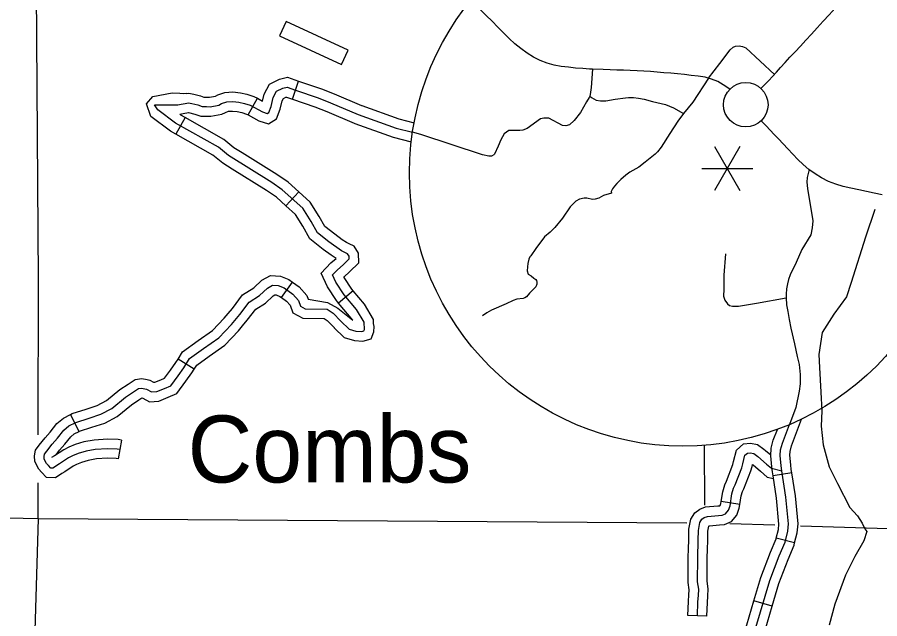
# Model space of a CAD drawing. Extents: x 0 to 3171, y 0 to 2059.
# Drawn here: x 1093.1 to 1206.3, y 496.2 to 575.3 of the extents above; entities that cross this region are included whole.
import ezdxf

# ---------------------------------------------------------------- set-up
doc = ezdxf.new("R2010")
doc.units = 0
for name, color, linetype in [('Level 10', 7, 'Continuous'), ('Level 24', 7, 'Continuous'), ('Level 32', 7, 'Continuous'), ('Level 35', 7, 'Continuous'), ('Level 45', 7, 'Continuous'), ('Level 48', 7, 'Continuous'), ('Level 5', 7, 'Continuous'), ('Level 57', 7, 'Continuous'), ('Level 63', 7, 'Continuous')]:
    doc.layers.add(name, color=color, linetype=linetype)

msp = doc.modelspace()

# ---------------------------------------------------------------- linework, layer by layer
at = {"layer": 'Level 10'}
for points in [[(1190.74, 565.9), (1191.3, 566.48), (1191.76, 566.96), (1192.25, 567.48), (1192.78, 568.04), (1193.33, 568.65), (1193.93, 569.3), (1194.55, 570), (1195.22, 570.72), (1195.92, 571.48), (1196.64, 572.26), (1197.38, 573.06), (1198.13, 573.89), (1198.9, 574.73), (1199.69, 575.58), (1200.48, 576.44), (1201.28, 577.31), (1202.08, 578.18), (1204.91, 581.19)], [(1170.04, 568.39), (1168.63, 568.45), (1168.24, 568.46), (1167.33, 568.51), (1166.4, 568.59), (1165.46, 568.69), (1164.52, 568.81), (1163.58, 568.97), (1162.65, 569.23), (1161.74, 569.58), (1160.86, 570.03), (1160.02, 570.55), (1159.22, 571.14), (1158.44, 571.79), (1157.68, 572.48), (1156.93, 573.22), (1156.18, 573.97), (1155.43, 574.73), (1154.67, 575.48), (1153.91, 576.23), (1153.15, 576.98), (1152.63, 577.5)], [(1183.68, 567.31), (1183.4, 567.39), (1182.51, 567.53), (1181.6, 567.63), (1180.69, 567.73), (1179.79, 567.82), (1178.89, 567.9), (1178.01, 567.98), (1177.12, 568.06), (1176.23, 568.14), (1175.34, 568.2), (1174.47, 568.22), (1173.56, 568.28), (1172.69, 568.31), (1171.81, 568.33), (1170.93, 568.35), (1170.04, 568.39)], [(1186.66, 565.8), (1185.8, 566.4), (1185.06, 566.82), (1184.26, 567.15), (1183.68, 567.31)], [(1206.66, 551.93), (1205.63, 552.15), (1204.61, 552.37), (1203.58, 552.58), (1202.56, 552.79), (1201.55, 553.02), (1200.56, 553.32), (1199.62, 553.7), (1198.71, 554.16), (1197.85, 554.68), (1197.04, 555.27), (1196.29, 555.91), (1195.6, 556.59), (1194.93, 557.28), (1194.29, 557.97), (1193.67, 558.63), (1193.07, 559.27), (1192.5, 559.87), (1191.95, 560.45), (1191.44, 560.99), (1190.78, 561.67)]]:
    msp.add_lwpolyline(points, dxfattribs=at)
at = {"layer": 'Level 24'}
msp.add_circle((1188.75, 563.77), 2.92, dxfattribs=at)
at = {"layer": 'Level 32'}
for p, q in [((1194.8, 515.4), (1192.33, 515.01)), ((1195.17, 506.19), (1192.75, 506.81)), ((1192.21, 497.87), (1189.81, 498.57))]:
    msp.add_line(p, q, dxfattribs=at)
for points in [[(1183.86, 567.26), (1185.36, 569.17), (1186.71, 570.99), (1187.11, 571.34), (1187.42, 571.47), (1187.87, 571.5), (1188.32, 571.44), (1188.77, 571.23), (1192.51, 567.76)], [(1183.86, 567.26), (1181.81, 564.1), (1180.57, 562.64), (1179.83, 561.61), (1178.77, 560.01), (1177.64, 558.18), (1177.17, 557.57), (1176.87, 557.28), (1175.54, 556.22), (1174.7, 555.57), (1173.52, 554.89), (1172.99, 554.5), (1172.32, 553.93), (1171.81, 553.43), (1171.5, 553.08), (1171.24, 552.72), (1171.09, 552.35), (1171.11, 552.17)], [(1197.07, 555.25), (1196.82, 554.19), (1196.79, 553.61), (1196.85, 552.76), (1197.57, 548.53), (1197.46, 547.58), (1197.29, 546.69), (1196.12, 544.73), (1195.37, 543.04), (1195.14, 542.55), (1194.84, 541.99), (1194.59, 541.44), (1194.37, 540.79), (1194.22, 540.24), (1194.1, 539.6), (1194.04, 538.86), (1194.05, 538.42), (1194.1, 537.49), (1194.26, 536.61), (1194.46, 535.57), (1194.68, 534.42), (1195.16, 532.37), (1195.52, 530.69), (1195.76, 529.65), (1195.89, 528.33), (1195.88, 527.1), (1195.76, 526.12), (1195.34, 524.01), (1194.48, 521.74)], [(1194.8, 515.4), (1194.73, 515.86), (1194.66, 516.47), (1194.53, 517.71), (1194.57, 518.23), (1194.75, 518.94), (1196.09, 522.47)], [(1190.08, 495.07), (1191.9, 501.24), (1193.14, 504.51), (1193.91, 506.31), (1194.29, 507.75), (1194.36, 508.69), (1194.03, 512.22), (1193.49, 515.69), (1193.42, 516.34), (1193.28, 517.68), (1193.33, 518.43), (1193.56, 519.32), (1194.48, 521.74)], [(1192.33, 515.01), (1192.25, 515.53), (1192.18, 516.21), (1192.03, 517.66), (1192.09, 518.63), (1192.37, 519.71), (1192.9, 521.12)], [(1192.75, 506.81), (1193.05, 507.95), (1193.1, 508.67), (1192.79, 512.07), (1192.33, 515.01)], [(1195.17, 506.19), (1195.52, 507.54), (1195.61, 508.7), (1195.27, 512.37), (1194.8, 515.4)], [(1189.81, 498.57), (1190.71, 501.64), (1191.98, 504.98), (1192.73, 506.72), (1192.75, 506.81)], [(1192.21, 497.87), (1193.08, 500.85), (1194.3, 504.04), (1195.1, 505.9), (1195.17, 506.19)], [(1187.32, 490.12), (1187.71, 491.5), (1188.88, 495.43), (1189.81, 498.57)], [(1189.73, 489.44), (1190.11, 490.81), (1191.28, 494.72), (1192.21, 497.87)]]:
    msp.add_lwpolyline(points, dxfattribs=at)
at = {"layer": 'Level 35'}
msp.add_lwpolyline([(1205.7, 550), (1204.46, 546.35), (1202.61, 540.42), (1201.96, 538.54), (1200.32, 536.25), (1198.78, 533.83), (1198.36, 530.97), (1198.43, 529.24), (1198.61, 526), (1198.75, 523.56), (1198.65, 521.54), (1198.92, 519.09), (1199.71, 516.21), (1200.81, 513.99), (1202.41, 510.86), (1203.43, 509.77), (1204.04, 508.79), (1204.38, 508.05), (1204.64, 507.69), (1204.26, 506.47), (1203.09, 504.41), (1201.83, 501.98), (1200.46, 498.14), (1199.72, 495.39)], dxfattribs=at)
at = {"layer": 'Level 45'}
for p, q in [((1129.2, 564.52), (1130.02, 566.88)), ((1123.4, 562.43), (1124.6, 564.62)), ((1115.11, 562.09), (1113.88, 559.91)), ((1130.04, 552.34), (1128.36, 550.49)), ((1127.77, 538.43), (1129.23, 540.46)), ((1137.19, 539.32), (1135.28, 537.71)), ((1116.3, 529.03), (1114.18, 530.35)), ((1101.19, 520.84), (1100.07, 523.08)), ((1106.77, 519.69), (1106.33, 517.23)), ((1187.98, 511.23), (1185.51, 511.63)), ((1183.65, 496.59), (1181.16, 496.68))]:
    msp.add_line(p, q, dxfattribs=at)
for points in [[(1168.63, 568.45), (1168.46, 566.02), (1168.33, 565.13), (1168.28, 564.9), (1168.18, 564.74), (1167.84, 564.17), (1167.04, 562.77), (1166.21, 561.7), (1165.61, 561.14), (1165.11, 560.99), (1164.7, 561.03), (1162.9, 562), (1162.24, 562.01), (1161.77, 561.94), (1160.04, 560.63), (1159.45, 560.43), (1159.06, 560.39), (1157.65, 560.39), (1157.02, 559.96), (1156.59, 559.18), (1156.25, 558.31), (1155.75, 557.26), (1155.65, 557.18), (1155.37, 557.03), (1155.02, 557.02), (1154.17, 557.17), (1146.09, 559.86), (1144.97, 560.15)], [(1124.6, 564.62), (1125.28, 564.25), (1125.51, 565.18), (1126.2, 566.48), (1127.5, 567.13), (1128.57, 567.39), (1130.02, 566.88)], [(1130.02, 566.88), (1133.01, 565.84), (1134.68, 565.19), (1138.29, 563.66)], [(1113.88, 559.91), (1113.18, 560.31), (1110.62, 562.24), (1110.06, 563.87), (1110.87, 564.87), (1113.39, 565.34), (1114.44, 565.3), (1114.9, 565.23), (1115.31, 565.3)], [(1111.11, 563.74), (1113.95, 563.74), (1114.15, 563.74), (1114.61, 563.84), (1115.1, 563.94), (1115.57, 564.02), (1115.98, 563.94), (1116.77, 563.74), (1117.37, 563.53), (1117.93, 563.53), (1118.4, 563.51), (1119.53, 563.71), (1119.91, 563.92), (1120.57, 564.14), (1121.36, 564.19), (1122.17, 564.12), (1122.9, 563.94), (1123.66, 563.71), (1125.29, 562.82), (1125.9, 562.62), (1126.1, 562.75), (1126.4, 563.56), (1126.68, 564.73), (1127.11, 565.54), (1127.93, 565.94), (1128.51, 566.08), (1129.61, 565.7)], [(1115.29, 565.24), (1115.59, 565.29), (1116.25, 565.16), (1117.12, 564.94), (1117.58, 564.78), (1117.97, 564.78), (1118.32, 564.77), (1119.12, 564.91), (1119.41, 565.06), (1120.32, 565.38), (1121.37, 565.45), (1122.37, 565.35), (1123.23, 565.15), (1124.15, 564.87), (1124.6, 564.62)], [(1129.61, 565.7), (1132.58, 564.67), (1134.21, 564.03), (1137.86, 562.49), (1142.82, 560.71), (1144.97, 560.15)], [(1123.4, 562.43), (1124.79, 561.67), (1126.06, 561.25), (1127.13, 561.92), (1127.59, 563.2), (1127.86, 564.28), (1128.03, 564.6), (1128.36, 564.76), (1128.45, 564.78), (1129.2, 564.52)], [(1129.2, 564.52), (1132.14, 563.5), (1133.74, 562.87), (1137.32, 561.36)], [(1168.28, 564.9), (1168.48, 564.7), (1169.12, 564.36), (1169.69, 564.28), (1170.39, 564.29), (1171.6, 564.51), (1172.96, 564.68), (1173.36, 564.7), (1174.01, 564.7), (1174.65, 564.63), (1175.39, 564.49), (1176.51, 564.19), (1178.2, 563.78), (1179.26, 563.37), (1180.57, 562.64)], [(1125.92, 539.69), (1126.59, 540.06), (1127.35, 540.01), (1128.14, 539.7), (1129.27, 538.89), (1130.02, 538.07), (1130.28, 537.31), (1130.9, 536.96), (1133.78, 536.91), (1134.55, 536.37), (1135.58, 535.35), (1136.65, 534.3), (1137.55, 534.04), (1138.32, 533.98), (1138.6, 534.06), (1138.66, 534.23), (1138.69, 534.55), (1138.61, 534.89), (1138.61, 535.21), (1137.64, 536.85), (1136, 538.8), (1134.91, 540.47), (1134.48, 541.4), (1135.12, 542.09), (1135.88, 542.73), (1136.66, 543.51), (1136.64, 543.89), (1136.45, 544.19), (1136.1, 544.36), (1135.64, 544.59), (1134.01, 545.75), (1132.48, 546.96), (1131.66, 548.44), (1130.58, 550.16), (1127.87, 552.61), (1126.5, 553.56), (1120.79, 557.1), (1119.48, 558.19), (1113.86, 561.36), (1111.54, 563.12), (1111.11, 563.74)], [(1138.29, 563.66), (1138.32, 563.65), (1143.19, 561.9), (1145.18, 561.39)], [(1115.11, 562.09), (1114.55, 562.41), (1114.41, 562.51), (1114.87, 562.62), (1115.56, 562.76)], [(1122.62, 557.44), (1121.52, 558.12), (1120.2, 559.22), (1115.11, 562.09)], [(1115.56, 562.76), (1116.41, 562.54), (1117.17, 562.28), (1117.9, 562.28), (1118.47, 562.25), (1119.94, 562.52), (1120.41, 562.77), (1120.82, 562.91), (1121.34, 562.94), (1121.96, 562.88), (1122.58, 562.73), (1123.18, 562.55), (1123.4, 562.43)], [(1137.32, 561.36), (1137.41, 561.32), (1142.46, 559.51), (1144.81, 558.9)], [(1121.3, 555.32), (1120.06, 556.09), (1118.77, 557.16), (1113.88, 559.91)], [(1130.04, 552.34), (1128.65, 553.59), (1127.18, 554.6), (1122.62, 557.44)], [(1128.36, 550.49), (1127.1, 551.63), (1125.82, 552.51), (1121.3, 555.32)], [(1135.76, 546.04), (1134.76, 546.75), (1133.45, 547.79), (1132.74, 549.08), (1131.55, 550.97), (1130.04, 552.34)], [(1171.11, 552.17), (1170.07, 551.84), (1169.45, 551.5), (1168.97, 551.35), (1168.64, 551.34), (1167.88, 551.48), (1167.51, 551.5), (1166.92, 551.35), (1166.42, 551.11), (1166.1, 550.77), (1165.7, 550.34), (1164.66, 548.85), (1163.65, 547.63), (1163.07, 547.01), (1162.3, 546.43), (1161.19, 544.88), (1160.51, 543.9), (1160.41, 543.77), (1160.26, 543.49), (1160.12, 542.92), (1160.06, 542.49), (1160.03, 541.96), (1160.17, 541.53), (1160.56, 541.27), (1160.93, 540.98), (1161.17, 540.82), (1161.26, 540.69), (1161.32, 540.47), (1161.32, 540.19), (1161.16, 539.84), (1160.77, 539.45), (1160.33, 539.01), (1159.93, 538.55), (1159.75, 538.42), (1159.51, 538.33), (1158.66, 538.23), (1158.2, 538.06), (1157.3, 537.63), (1155.34, 536.8), (1154.74, 536.41), (1154.18, 536.04)], [(1134.31, 544), (1133.26, 544.75), (1131.5, 546.14), (1130.58, 547.81), (1129.62, 549.35), (1128.36, 550.49)], [(1137.19, 539.32), (1137, 539.55), (1136.01, 541.07), (1135.97, 541.16), (1135.99, 541.18), (1136.72, 541.81), (1137.93, 543.01), (1137.88, 544.29), (1137.3, 545.17), (1136.65, 545.48), (1136.29, 545.66), (1135.76, 546.04)], [(1135.28, 537.71), (1134.99, 538.05), (1133.81, 539.86), (1133, 541.63), (1134.26, 542.99), (1134.93, 543.56), (1134.31, 544)], [(1186.09, 544.18), (1185.85, 541.39), (1185.85, 539.55), (1185.84, 538.63), (1186.01, 538.1), (1186.33, 537.6), (1186.6, 537.4), (1187, 537.29), (1187.81, 537.31), (1190.14, 537.71), (1194.05, 538.42)], [(1120.76, 536.33), (1121.33, 537.01), (1122.66, 538.79), (1124.12, 539.71), (1125.17, 540.7), (1126.31, 541.33), (1127.63, 541.24), (1128.75, 540.8), (1129.23, 540.46)], [(1129.23, 540.46), (1130.11, 539.83), (1131.12, 538.72), (1131.29, 538.21), (1133.81, 537.8), (1135.17, 537.05), (1137.16, 535.48)], [(1106.55, 518.46), (1106.19, 518.53), (1104.92, 518.58), (1103.3, 518.48), (1102.1, 518.25), (1101.07, 517.93), (1100.34, 517.63), (1099.8, 517.36), (1098.63, 516.6), (1097.74, 516.03), (1097.46, 516.04), (1097.15, 516.37), (1096.91, 516.62), (1096.6, 517.21), (1096.59, 517.55), (1096.65, 517.87), (1096.96, 518.27), (1097.67, 519.19), (1098.37, 519.96), (1099.19, 521.01), (1099.82, 521.56), (1100.76, 522.03), (1102.49, 522.59), (1104.06, 523.1), (1105.48, 523.86), (1107.3, 525.33), (1109.01, 526.48), (1109.37, 526.53), (1109.83, 526.43), (1110.03, 526.38), (1110.69, 526.03), (1111.4, 526.08), (1112.41, 526.48), (1113.23, 526.84), (1114.19, 528.16), (1114.95, 529.22), (1115.71, 530.44), (1117.54, 531.76), (1119.52, 533.13), (1121.19, 534.91), (1122.31, 536.23), (1123.52, 537.85), (1124.89, 538.72), (1125.92, 539.69)], [(1134.67, 534.5), (1134.7, 534.47), (1135.99, 533.18), (1137.34, 532.8), (1138.44, 532.72), (1139.54, 533.02), (1139.89, 533.95), (1139.95, 534.63), (1139.86, 535.04), (1139.85, 535.56), (1138.66, 537.58), (1137.19, 539.32)], [(1122.67, 534.72), (1123.28, 535.45), (1124.39, 536.92), (1125.66, 537.72), (1126.66, 538.67), (1126.88, 538.79), (1127.07, 538.78), (1127.54, 538.59), (1127.77, 538.43)], [(1127.77, 538.43), (1128.43, 537.95), (1128.92, 537.42), (1129.25, 536.45), (1130.57, 535.72), (1133.38, 535.67), (1133.75, 535.41), (1134.67, 534.5)], [(1137.16, 535.48), (1135.28, 537.71)], [(1114.18, 530.35), (1114.78, 531.31), (1116.82, 532.78), (1118.7, 534.09), (1120.26, 535.74), (1120.76, 536.33)], [(1116.3, 529.03), (1116.64, 529.57), (1118.26, 530.74), (1120.34, 532.18), (1122.12, 534.08), (1122.67, 534.72)], [(1107.63, 527.05), (1108.55, 527.68), (1109.42, 527.8), (1110.11, 527.65), (1110.48, 527.56), (1110.96, 527.3), (1111.12, 527.31), (1111.93, 527.64), (1112.41, 527.85), (1113.18, 528.89), (1113.91, 529.92), (1114.18, 530.35)], [(1109.02, 524.98), (1109.41, 525.24), (1109.54, 525.21), (1109.57, 525.21), (1110.42, 524.75), (1111.68, 524.84), (1112.9, 525.33), (1114.04, 525.83), (1115.2, 527.43), (1115.99, 528.53), (1116.3, 529.03)], [(1100.07, 523.08), (1100.29, 523.19), (1102.1, 523.78), (1103.57, 524.25), (1104.79, 524.9), (1106.56, 526.34), (1107.63, 527.05)], [(1101.19, 520.84), (1101.23, 520.87), (1102.87, 521.4), (1104.55, 521.94), (1106.17, 522.81), (1108.05, 524.32), (1109.02, 524.98)], [(1098.93, 515.3), (1098.08, 514.76), (1096.91, 514.81), (1096.24, 515.51), (1095.88, 515.89), (1095.36, 516.88), (1095.33, 517.65), (1095.48, 518.39), (1095.96, 519.03), (1096.72, 519.99), (1097.41, 520.76), (1098.28, 521.88), (1099.12, 522.61), (1100.07, 523.08)], [(1098.16, 517.78), (1098.63, 518.38), (1099.33, 519.16), (1100.1, 520.15), (1100.52, 520.51), (1101.19, 520.84)], [(1106.77, 519.69), (1106.32, 519.77), (1104.91, 519.83), (1103.15, 519.72), (1101.8, 519.46), (1100.65, 519.11), (1099.83, 518.76), (1099.18, 518.45), (1097.95, 517.65), (1097.57, 517.4)], [(1185.51, 511.63), (1185.72, 512.91), (1185.98, 513.83), (1186.2, 514.3), (1187.04, 516.48), (1187.16, 516.89), (1187.52, 518.39), (1188.46, 519.21), (1189.36, 519.29), (1190.3, 519.14), (1191.14, 518.52), (1191.36, 518.33)], [(1182.4, 496.63), (1182.47, 498.45), (1182.52, 499.29), (1182.57, 500.11), (1182.43, 501.09), (1182.45, 504.23), (1182.51, 506.56), (1182.52, 507.85), (1182.73, 508.86), (1182.99, 509.31), (1183.3, 509.54), (1183.71, 509.69), (1185.19, 509.81), (1185.66, 509.86), (1186.1, 510.04), (1186.47, 510.49), (1186.68, 511.07), (1186.94, 512.64), (1187.15, 513.39), (1187.35, 513.81), (1188.23, 516.08), (1188.37, 516.57), (1188.64, 517.71), (1188.98, 518), (1189.32, 518.03), (1189.8, 517.96), (1190.35, 517.55), (1191.49, 516.56), (1192.14, 516), (1193.49, 515.69)], [(1191.36, 518.33), (1192.02, 517.76)], [(1106.33, 517.23), (1106.05, 517.28), (1104.93, 517.33), (1103.46, 517.23), (1102.4, 517.03), (1101.5, 516.75), (1100.86, 516.49), (1100.42, 516.27), (1099.31, 515.55), (1098.93, 515.3)], [(1187.98, 511.23), (1188.16, 512.37), (1188.33, 512.95), (1188.5, 513.32), (1189.41, 515.68), (1189.58, 516.25), (1189.64, 516.51), (1189.72, 516.44)], [(1189.72, 516.44), (1190.67, 515.62), (1191.56, 514.85), (1192.39, 514.66)], [(1181.23, 505.45), (1181.26, 506.58), (1181.27, 507.99), (1181.55, 509.31), (1182.04, 510.16), (1182.7, 510.65), (1183.44, 510.92), (1185.08, 511.05), (1185.34, 511.08), (1185.37, 511.12), (1185.47, 511.39), (1185.51, 511.63)], [(1183.73, 505.39), (1183.76, 506.53), (1183.77, 507.72), (1183.91, 508.41), (1183.93, 508.44), (1183.99, 508.46), (1185.3, 508.56), (1185.97, 508.63), (1186.86, 509.01), (1187.57, 509.85), (1187.9, 510.76), (1187.98, 511.23)], [(1181.16, 496.68), (1181.23, 498.5), (1181.27, 499.36), (1181.31, 500.05), (1181.18, 501.01), (1181.2, 504.25), (1181.23, 505.45)], [(1183.65, 496.59), (1183.72, 498.39), (1183.77, 499.22), (1183.82, 500.16), (1183.68, 501.17), (1183.7, 504.21), (1183.73, 505.39)]]:
    msp.add_lwpolyline(points, dxfattribs=at)
at = {"layer": 'Level 48'}
for p, q in [((1187.99, 558.28), (1184.66, 552.51)), ((1184.66, 558.28), (1187.99, 552.51)), ((1182.99, 555.39), (1189.66, 555.39))]:
    msp.add_line(p, q, dxfattribs=at)
at = {"layer": 'Level 5'}
for points in [[(1095.82, 520.39), (1095.84, 540.83), (1095.44, 597.82)], [(1183.38, 511.16), (1183.35, 519.02)], [(1095.81, 509.35), (1095.81, 514.11)], [(1095.81, 509.35), (1029.42, 510.84)], [(1095.81, 509.35), (1093.18, 421.22)], [(1181.03, 508.8), (1095.81, 509.35)], [(1192.57, 508.51), (1186.67, 508.69)], [(1267.61, 506.06), (1260.77, 506.42), (1195.93, 508.4)]]:
    msp.add_lwpolyline(points, dxfattribs=at)
at = {"layer": 'Level 57'}
for p, q in [((1128.4, 574.7), (1127.52, 572.81)), ((1136.53, 570.93), (1128.4, 574.7)), ((1127.52, 572.81), (1135.65, 569.04)), ((1135.65, 569.04), (1136.53, 570.93))]:
    msp.add_line(p, q, dxfattribs=at)
at = {"layer": 'Level 63'}
msp.add_circle((1180.5, 554.83), 35.92, dxfattribs=at)

# ---------------------------------------------------------------- texts
at = {"layer": 'Level 24'}
msp.add_text('Combs', height=8.8, dxfattribs=at).set_placement((1115.44, 514.14))

doc.saveas('drawing.dxf')
